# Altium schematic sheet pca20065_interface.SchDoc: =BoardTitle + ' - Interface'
size A3; Organization: Nordic Semiconductor; DocumentNumber: 8; SheetNumber: 8; SheetTotal: 10; CompanyName: Nordic Semiconductor; DocumentSize: A3
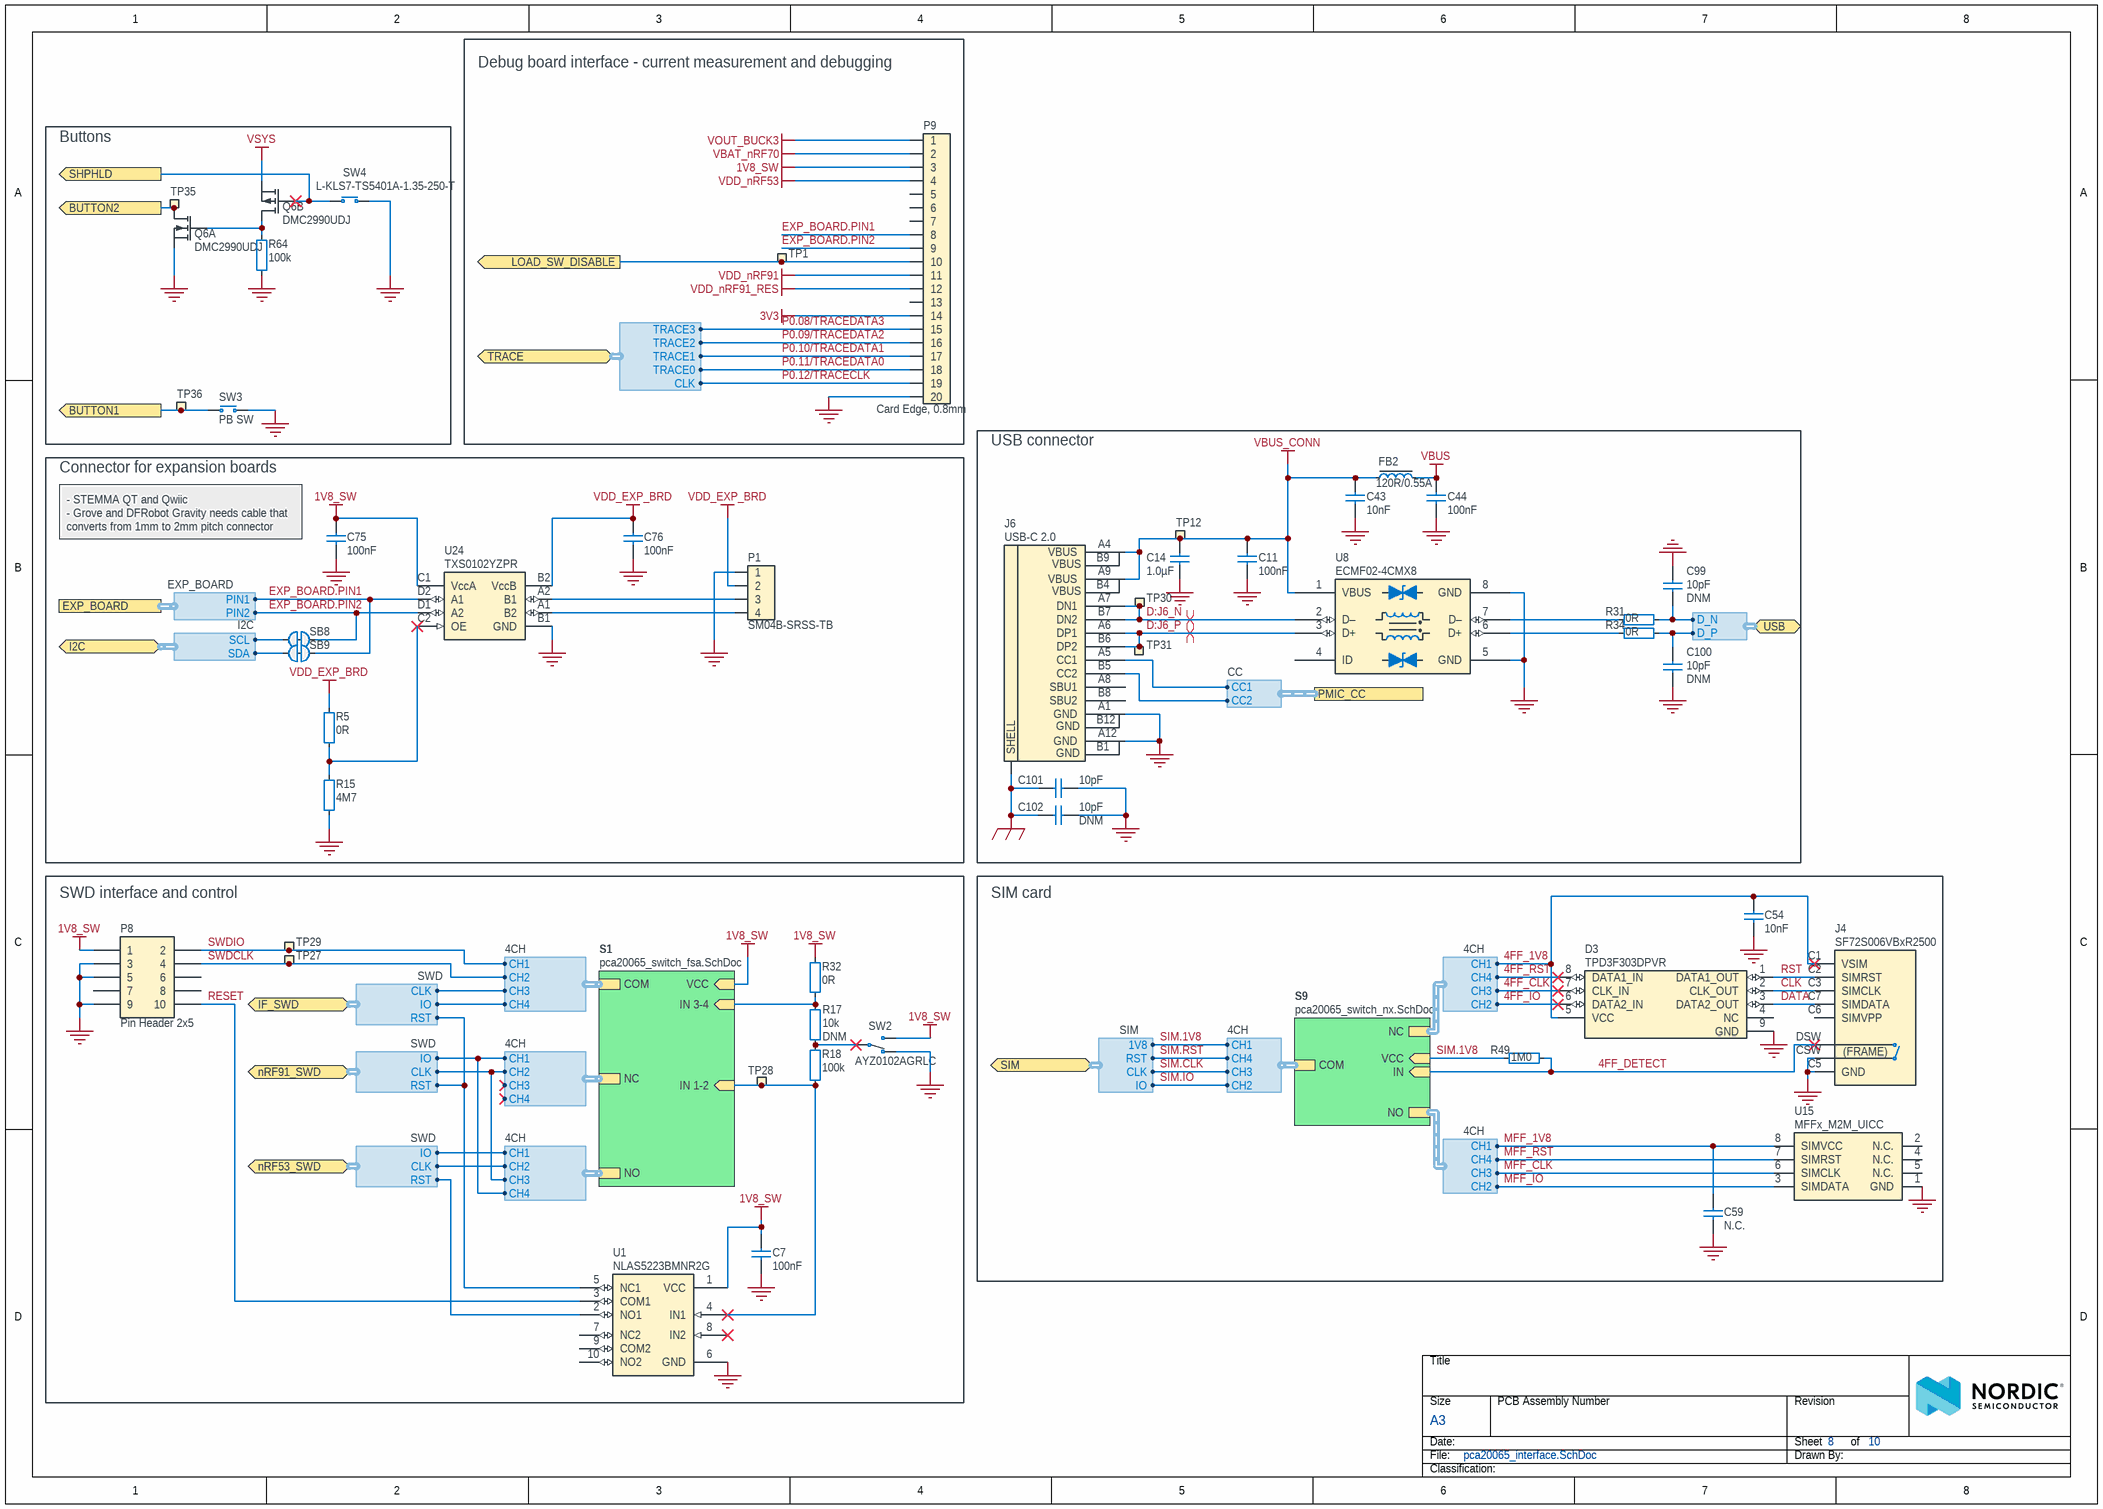
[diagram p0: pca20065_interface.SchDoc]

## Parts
C7  100nF  [CAPC0603X03L_C]
C11  100nF  [CAPC0603X03L_C]
C14  1.0µF  [CAPC1005X04L]
C43  10nF  [CAPC0603X03L_C]
C44  100nF  [CAPC0603X03L_C]
C54  10nF  [CAPC0603X03L_C]
C59  N.C.  [CAPC0603X03L_C_NC]
C75  100nF  [CAPC0603X03L_C]
C76  100nF  [CAPC0603X03L_C]
C99  10pF  Assembly: DNM  [CAPC0603X03L_C]
C100  10pF  Assembly: DNM  [CAPC0603X03L_C]
C101  10pF  [CAPC0603X03L_C]
C102  10pF  Assembly: DNM  [CAPC0603X03L_C]
D3  TPD3F303DPVR  [SON50P210X160X65_HS-9N]
FB2  120R/0.55A  [INDC1005X04L]
J4  SF72S006VBxR2500  [SF72S006VBxR2500]
J6  USB-C 2.0  [USB4110]
P1  SM04B-SRSS-TB  [SM04B-SRSS-TB]
P8  Pin Header 2x5  [HDR_2x5-SMD-1.27mm-ANG]
P9  Card Edge, 0.8mm  [10056847-101LF]
Q6  DMC2990UDJ  [SOTFL35P100X50-6N]  (parts A,B of 2)
R5  0R  [RESC0603X03L_C]
R15  4M7  [RESC0603X03L_C]
R17  10k  Assembly: DNM  [RESC0603X03L_C]
R18  100k  [RESC0603X03L_C]
R31  0R  [RESC0603X03L_C]
R32  0R  [RESC0603X03L_C]
R34  0R  [RESC0603X03L_C]
R49  1M0  [RESC0603X03L_C]
R64  100k  [RESC0603X03L_C]
SB8  Solderbridge  [Solderbridge_Shorted]  (value not drawn)  (net tie, no BOM)
SB9  Solderbridge  [Solderbridge_Shorted]  (value not drawn)  (net tie, no BOM)
SW2  AYZ0102AGRLC  [AYZ0102AGRLC]
SW3  PB SW  [L-KLS7-TS6616B-2.5-160-T]
SW4  L-KLS7-TS5401A-1.35-250-T  [L-KLS7-TS5401A-1.35-250-T]
TP1  Ø1.5mm,SMD  [TP_SMD_D1.5mm]  (value not drawn)  (no BOM)
TP12  Ø1.5mm,SMD  [TP_SMD_D1.5mm]  (value not drawn)  (no BOM)
TP27  Ø1.5mm,SMD  [TP_SMD_D1.5mm]  (value not drawn)  (no BOM)
TP28  Ø1.5mm,SMD  [TP_SMD_D1.5mm]  (value not drawn)  (no BOM)
TP29  Ø1.5mm,SMD  [TP_SMD_D1.5mm]  (value not drawn)  (no BOM)
TP30  Ø1.5mm,SMD  [TP_SMD_D1.5mm]  (value not drawn)  (no BOM)
TP31  Ø1.5mm,SMD  [TP_SMD_D1.5mm]  (value not drawn)  (no BOM)
TP35  Ø1.5mm,SMD  [TP_SMD_D1.5mm]  (value not drawn)  (no BOM)
TP36  Ø1.5mm,SMD  [TP_SMD_D1.5mm]  (value not drawn)  (no BOM)
U1  NLAS5223BMNR2G  [UFQFN40P140X180X55-10N]
U8  ECMF02-4CMX8  [UFDFN50P120X250X55-8N]
U15  MFFx_M2M_UICC  [SON127P600X90_HS-8N]
U24  TXS0102YZPR  [BGA8C50P2X4_89X189X50]

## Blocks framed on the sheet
Debug board interface - current measurement and debugging: P9 TP1
Buttons: Q6 R64 SW3 SW4 TP35 TP36
USB connector: C11 C14 C43 C44 C99-C102 FB2 J6 R31 R34 TP12 TP30 TP31 U8
Connector for expansion boards: C75 C76 P1 R5 R15 SB8 SB9 U24
SWD interface and control: C7 P8 R17 R18 R32 SW2 TP27-TP29 U1
SIM card: C54 C59 D3 J4 R49 U15

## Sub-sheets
S1 = pca20065_switch_fsa.SchDoc: IN 1-2 (in), COM (harness 4CH), NC (harness 4CH), NO (harness 4CH), IN 3-4 (in), VCC (in)
S9 = pca20065_switch_nx.SchDoc: IN (in), COM (harness 4CH), NC (harness 4CH), NO (harness 4CH), VCC (in)

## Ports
BUTTON1 (out), BUTTON2 (out), EXP_BOARD (harness EXP_BOARD), I2C (bidir, harness I2C), IF_SWD (bidir, harness SWD), LOAD_SW_DISABLE (out), nRF53_SWD (bidir, harness SWD), nRF91_SWD (bidir, harness SWD), PMIC_CC (harness CC), SHPHLD (out), SIM (bidir, harness SIM), TRACE (bidir, harness TRACE), USB (bidir, harness USB)

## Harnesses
SWD: IO, CLK, RST
SIM: RST, CLK, IO, 1V8
USB: D_N, D_P
EXP_BOARD: PIN1, PIN2
CC: CC2, CC1
4CH: CH1, CH2, CH3, CH4
I2C: SDA, SCL
TRACE: TRACE3, TRACE2, TRACE1, TRACE0, CLK

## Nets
1V8_SW: C7.1 C75.2 P8.1 P9.3 R32.1 SW2.3(N.O) U1.1(VCC) U24.C1(VccA) ; sheet S1/VCC
3V3: P9.14
GND: C7.2 C11.1 C14.1 C43.1 C44.1 C54.2 C59.1 C75.1 C76.1 C99.2 C100.2 C101.1 C102.1 D3.9(GND) J4.0(GND) J4.C5(GND) J4.CSW J6.A1(GND) J6.A12(GND) P1.1 P8.3 P8.5 P8.9 P9.20 Q6.1(S1) R15.2 R64.2 SW2.1(N.C) SW3.1(N.O) SW4.2(COM) U1.6(GND) U8.5(GND) U8.8(GND) U15.1(GND) U24.B1(GND)
Shield: C101.2 C102.2 J6.SHLD(SHELL)
VBAT_nRF70: P9.2
VBUS: C44.2 FB2.2
VBUS_CONN: C11.2 C14.2 C43.2 FB2.1 J6.A4(VBUS) J6.A9(VBUS) TP12.1 U8.1(VBUS)
VDD_EXP_BRD: C76.2 P1.2 R5.1 U24.B2(VccB)
VDD_nRF53: P9.4
VDD_nRF91: P9.11
VDD_nRF91_RES: P9.12
VOUT_BUCK3: P9.1
VSYS: Q6.4(S2)
4FF_1V8: C54.1 D3.5(VCC) J4.C1(VSIM) ; sheet S9/NC.CH1
4FF_CLK: D3.7(CLK_IN) ; sheet S9/NC.CH3
4FF_DETECT: J4.DSW R49.1 ; sheet S9/IN
4FF_IO: D3.6(DATA2_IN) ; sheet S9/NC.CH2
4FF_RST: D3.8(DATA1_IN) ; sheet S9/NC.CH4
BUTTON1: SW3.2(COM) TP36.1 ; port BUTTON1
BUTTON2: Q6.6(D1) TP35.1 ; port BUTTON2
CLK: D3.2(CLK_OUT) J4.C3(SIMCLK)
D:J6_N: J6.A7(DN1) J6.B7(DN2) TP30.1 U8.2(D–)
D:J6_P: J6.A6(DP1) J6.B6(DP2) TP31.1 U8.3(D+)
DATA: D3.3(DATA2_OUT) J4.C7(SIMDATA)
EXP_BOARD.PIN1: P9.8 SB9.1 U24.D2(A1) ; port EXP_BOARD.PIN1
EXP_BOARD.PIN2: P9.9 SB8.1 U24.D1(A2) ; port EXP_BOARD.PIN2
LOAD_SW_DISABLE: P9.10 TP1.1 ; port LOAD_SW_DISABLE
MFF_1V8: C59.2 U15.8(SIMVCC) ; sheet S9/NO.CH1
MFF_CLK: U15.6(SIMCLK) ; sheet S9/NO.CH3
MFF_IO: U15.3(SIMDATA) ; sheet S9/NO.CH2
MFF_RST: U15.7(SIMRST) ; sheet S9/NO.CH4
P0.08/TRACEDATA3: P9.15 ; port TRACE.TRACE3
P0.09/TRACEDATA2: P9.16 ; port TRACE.TRACE2
P0.10/TRACEDATA1: P9.17 ; port TRACE.TRACE1
P0.11/TRACEDATA0: P9.18 ; port TRACE.TRACE0
P0.12/TRACECLK: P9.19 ; port TRACE.CLK
RESET: P8.10 U1.3(COM1)
RST: D3.1(DATA1_OUT) J4.C2(SIMRST)
SHPHLD: Q6.5(G2) SW4.1(N.O) ; port SHPHLD
SIM.1V8: R49.2 ; sheet S9/VCC, port SIM.1V8, sheet S9/COM.CH1
SIM.CLK: port SIM.CLK, sheet S9/COM.CH3
SIM.IO: port SIM.IO, sheet S9/COM.CH2
SIM.RST: port SIM.RST, sheet S9/COM.CH4
SWDCLK: P8.4 TP27.1 ; sheet S1/COM.CH2
SWDIO: P8.2 TP29.1 ; sheet S1/COM.CH1
NetC99_1: C99.1 R31.1 ; port USB.D_N
NetC100_1: C100.1 R34.1 ; port USB.D_P
NetJ6_A5: J6.A5(CC1) ; port PMIC_CC.CC1
NetJ6_B5: J6.B5(CC2) ; port PMIC_CC.CC2
NetP1_3: P1.3 U24.A2(B1)
NetP1_4: P1.4 U24.A1(B2)
NetQ6_2: Q6.2(G1) Q6.3(D2) R64.1
NetR5_2: R5.2 R15.1 U24.C2(OE)
NetR17_1: R17.1 R32.2 ; sheet S1/IN 3-4
NetR17_2: R17.2 R18.1 SW2.2(COM)
NetR18_2: R18.2 TP28.1 U1.4(IN1) ; sheet S1/IN 1-2
NetR31_2: R31.2 U8.7(D–)
NetR34_2: R34.2 U8.6(D+)
NetSB8_2: SB8.2 ; port I2C.SCL
NetSB9_2: SB9.2 ; port I2C.SDA
NetU1_2: U1.2(NO1) ; port nRF53_SWD.RST
NetU1_5: U1.5(NC1) ; port nRF91_SWD.RST, port IF_SWD.RST
(unnamed): port nRF91_SWD.IO, sheet S1/NO.CH4, sheet S1/NC.CH1
(unnamed): port nRF91_SWD.CLK, sheet S1/NO.CH3, sheet S1/NC.CH2  [a separate net that carries the same name]
(unnamed): port nRF53_SWD.IO, sheet S1/NO.CH1  [a separate net that carries the same name]
(unnamed): port nRF53_SWD.CLK, sheet S1/NO.CH2  [a separate net that carries the same name]
(unnamed): sheet S1/COM.CH3, port IF_SWD.CLK  [a separate net that carries the same name]
(unnamed): sheet S1/COM.CH4, port IF_SWD.IO  [a separate net that carries the same name]

Not connected (* = marked no-connect by the designer): D3 4(NC); J4 C6(SIMVPP); J6 A8(SBU1) B8(SBU2); P8 6 7 8; P9 5 6 7 13; U1 7(NC2) 8(IN2)* 9(COM2) 10(NO2); U8 4(ID); U15 2(N.C.) 4(N.C.) 5(N.C.)

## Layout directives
differential pair: D:J6_N, D:J6_P

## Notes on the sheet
- (near C75) - STEMMA QT and Qwiic
  - Grove and DFRobot Gravity needs cable that converts from 1mm to 2mm pitch connector

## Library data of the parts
C7 = C0201-100n: Capacitor, X5R, ±10%; Manufacturer: N.A.; Part number IPS: 00000001248, 00000002505; Part number Norautron: 262071862; Part number NEMS: 100200078; Note: 16V; Pad Count: 2; Component Status: Active
C11 C44 = C0201-100n-25V-X5R: Capacitor, Ceramic, X5R, ±10%, 25V; Manufacturer: Murata; Manufacturer Part Number: GRM033R61E104KE14J; Part number NEMS: 100200459; Artikkelnr Noca: N.A.; Pad Count: 2; Component Status: Active
C14 = C0402-1µ0-10V-X5R: Capacitor, Ceramic, X5R, ±10%, 10V; Manufacturer: N.A.; Part number NEMS: 100200482; Pad Count: 2; Component Status: Active
C43 = C0201-10n-25V-X5R: Capacitor, Ceramic, X5R, ±10%, 25V; Manufacturer: Murata; Manufacturer Part Number: GRM033R61E103KA12D; Part number NEMS: 100200458; Artikkelnr Noca: N.A.; Pad Count: 2; Component Status: Active
C54 = C0201-10n: Capacitor, X7R, ±10%; Manufacturer: N.A.; Part number IPS: 00000003480; Part number Norautron: 26621779; Part number NEMS: 100200067; Note: 10V; Pad Count: 2; Component Status: Active
C59 = C0201-N.C.: Not mounted; Manufacturer: N.A.; Part number NEMS: 100200001; Note: Chip Cap; Assembly: Not mounted; Pad Count: 2; Component Status: Active
C75 C76 = C0201-100n-25V-X5R: Capacitor, Ceramic, X5R, ±10%, 25V; Manufacturer: Murata; Manufacturer Part Number: GRM033R61E104KE14J; Part number NEMS: 100200459; Pad Count: 2; Artikkelnr Noca: N.A.; Component Status: Active
C99-C102 = C0201-10p: Capacitor, C0G, ±5%, 25V; Manufacturer: Murata; Manufacturer Part Number: GRM0335C1E100JA01D; Part number IPS: 00000003191; Part number NEMS: 100200032; Note: Chip Cap 1%; Artikkelnr Noca: N.A.; Pad Count: 2; Component Status: Active
D3 = TPD3F303DPVR: ESD Protection and EMI Filter for SIM Card Interface; Manufacturer: Texas Instruments; Part number NEMS: 101900729; Note: N.A.; Pad Count: 8; Component Status: Active
FB2 = FB0402-120R@100M-500mA: Ferrite Bead, 120 Ohm @ 100MHz, 500mA, 250 mOhm Max; Manufacturer: Murata; Manufacturer Part Number: BLM15AG121SN1D; Part number IPS: 00000009954; Part number Norautron: 265230631; Part number NEMS: 100300099; Note: Chip EMIFIL Inductor Type Chip Ferrite Bead; Artikkelnr Noca: 33029317; Pad Count: 2; Component Status: Active
J4 = SF72S006VBDR2500: n 8 (6 + 2) Position Card Connector NANO SIM Surface Mount, Right Angle Gold; Manufacturer: JAE Electronics; Part number NEMS: 100500780; Note: N.A.; Pad Count: 8; Component Status: Active
J6 = USB4110-GF-A: USB-C Receptacle, 16 Pin, USB 2.0; Manufacturer: Global Connector Technology; Part number NEMS: 100500735; Pad Count: 16; Note: N.A.; Component Status: Active; System: Connector
P1 = SM04B-SRSS-TB: JST SR/SH 1.0mm 4-pin; Manufacturer: JST Sales America Inc.; Part number NEMS: 100500540; Note: N.A.; Pad Count: 4; Component Status: Active; System: Connector
P8 = Pin Header 2x5 SMD, 1.27mm, Angled: Pin Header 2x5, 1.27mm (50mil); Manufacturer: WCON; Manufacturer Part Number: 1325B-1205S0Z080CR04; Part number NEMS: 100500257; Note: (Replaced 1325B-1205S0Z080CR02); Artikkelnr Noca: N.A.; Pad Count: 10; Component Status: Active; System: Connector
P9 = 10056847-101LF: 0.8mm pitch, dual edge, right angle, SMD, card edge connector; Manufacturer: FCI; Part number NEMS: 100500633; Note: N.A.; Pad Count: 20; Component Status: Active
Q6 = DMC2990UDJ-7: MOSFET, Dual N and P-Channel, 20V, 450mA/310mA, 990mOhm, 350mW; Manufacturer: Diodes Incorporated; Part number IPS: 00000004489; Part number Norautron: 26470028; Part number NEMS: 101300174; Note: N.A.; Pad Count: 6; Component Status: Active
R5 R31 R32 R34 = R0201-0R: Resistor, ±5%, 0.05W; Manufacturer: N.A.; Part number IPS: 00000003245; Part number NEMS: 100100001; Note: Chip Res 5%; Pad Count: 2; Component Status: Active
R15 = R0201-4M7: Resistor, ±1%, 0.05W; Manufacturer: N.A.; Part number NEMS: 100100101; Note: Chip Res 1%; Pad Count: 2; Component Status: Active
R17 = R0201-10k: Resistor, ±1%, 0.05W; Manufacturer: N.A.; Part number IPS: 00000001255; Part number Norautron: 26107101; Part number NEMS: 100100065; Note: Chip Res 1%; Pad Count: 2; Component Status: Active
R18 R64 = R0201-100k: Resistor, ±1%, 0.05W; Manufacturer: N.A.; Part number IPS: 00000001419; Part number Norautron: 26108487; Part number NEMS: 100100080; Note: Chip Res 1%; Pad Count: 2; Component Status: Active
R49 = R0201-1M0: Resistor, ±1%, 0.05W; Manufacturer: N.A.; Part number IPS: 00000001418; Part number Norautron: 26107108; Part number NEMS: 100100093; Note: Chip Res 1%; Pad Count: 2; Component Status: Active
SB8 SB9 = Solderbridge Shorted: Shorted Solderbridge; Manufacturer: N.A.; Part number NEMS: 100500459; Component Status: Active; Pad Count: 2; System: Connector
SW2 = AYZ0102AGRLC: Miniature slide switch, SPDT, Right-Angle, ON-ON, 12V, 100mA; Manufacturer: C&K; Part number IPS: 00000002488; Part number NEMS: 101500120; Note: N.A.; Pad Count: 3; Component Status: Active
SW3 = L-KLS7-TS6616B-2.5-160-T: Tactile Switch, SPNO, SMD, 160gf, 6.2x6.4x2.5mm; Manufacturer: KLS; Part number NEMS: 101500133, 101500001; Note: N.A.; Pad Count: 4; Component Status: Active
SW4 = L-KLS7-TS5401A-1.35-250-T: Microminiature SMT Switch, Side Actuated; Manufacturer: Cabcon; Part number NEMS: 101500149; Pad Count: 4; Note: Tactile Switch, SPST, SMD, 220gf; Artikkelnr Noca: N.A.; Component Status: Active
TP1 TP12 TP27-TP31 = TP_SMD_Ø1.5MM: 1.5mm circular SMD testpad; Manufacturer: Nordic Semiconductor; Manufacturer Part Number: N.A.; Part number NEMS: 100500477; Pad Count: 1; Component Status: Active
TP35 TP36 = TP_SMD_Ø1.5MM: 1.5mm circular SMD testpad; Manufacturer: Nordic Semiconductor; Manufacturer Part Number: N.A.; Part number NEMS: 100500477; Pad Count: 1; Component Status: Active; System: Connector
U1 = NLAS5223BMNR2G: Dual-SPDT Analog Switch; Manufacturer: ON Semiconductor; Part number NEMS: 101900819; Note: N.A.; Pad Count: 10; Component Status: Active
U8 = ECMF02-4CMX8: 2 Line Common mode filter with ESD protection for USB 2.0 interface; Manufacturer: STMicroelectronics; Part number NEMS: 100800034; Component Status: Active; Pad Count: 8; Note: N.A.
U15 = M2M_UICC: M2M UICC SIM Card; Manufacturer: N.A.; Part number NEMS: 101900595; Pad Count: 8; Component Status: Active
U24 = TXS0102YZPR: Voltage Level Translator Bidirectional 1 Circuit 2 Channel 24Mbps 8-DSBGA; Manufacturer: Texas Instruments; Part number NEMS: 101900724; Pad Count: 8; Note: TEXAS INSTRUMENTS - TXS0102YZTR - IC, TRANSLATOR; Artikkelnr Noca: N.A.; Component Status: Active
